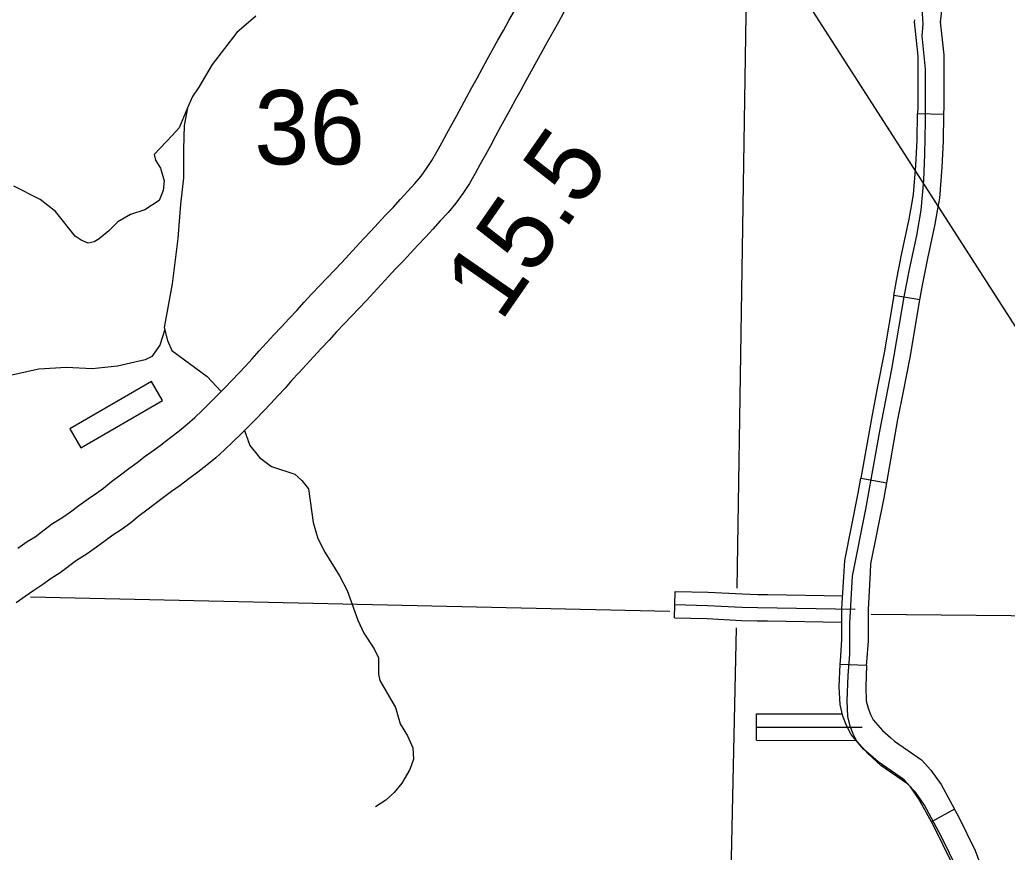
# Model space of a CAD drawing. Extents: x 0 to 3171, y 0 to 2059.
# Drawn here: x 1872.3 to 1965.7, y 1087.6 to 1166.4 of the extents above; entities that cross this region are included whole.
import ezdxf

# ---------------------------------------------------------------- set-up
doc = ezdxf.new("R2010")
doc.units = 0
for name, color, linetype in [('Default', 7, 'Continuous'), ('Level 10', 7, 'Continuous'), ('Level 31', 7, 'Continuous'), ('Level 35', 7, 'Continuous'), ('Level 4', 7, 'Continuous'), ('Level 45', 7, 'Continuous'), ('Level 48', 7, 'Continuous'), ('Level 5', 7, 'Continuous'), ('Level 57', 7, 'Continuous')]:
    doc.layers.add(name, color=color, linetype=linetype)

msp = doc.modelspace()

# ---------------------------------------------------------------- linework, layer by layer
at = {"layer": 'Default'}
for points in [[(1931.872, 1191.314), (2273.758, 658.86), (2637.036, 658.323)], [(1931.872, 1191.314), (2119.81, 898.62)]]:
    msp.add_lwpolyline(points, dxfattribs=at)
at = {"layer": 'Level 10'}
for p, q in [((1885.775, 1126.293), (1885.767, 1126.287)), ((1888.288, 1122.969), (1888.281, 1122.964))]:
    msp.add_line(p, q, dxfattribs=at)
for points in [[(1885.767, 1126.287), (1886.579, 1126.904), (1887.369, 1127.517), (1888.12, 1128.133), (1888.836, 1128.768), (1889.544, 1129.445), (1890.262, 1130.156), (1890.976, 1130.87), (1891.672, 1131.576), (1892.353, 1132.273), (1893.011, 1132.954), (1893.648, 1133.637), (1894.276, 1134.329), (1894.922, 1135.07), (1895.622, 1135.834), (1896.329, 1136.599), (1897.045, 1137.36), (1897.762, 1138.135), (1898.491, 1138.911), (1899.196, 1139.692), (1899.935, 1140.48), (1900.658, 1141.247), (1901.374, 1141.998), (1902.073, 1142.728), (1902.747, 1143.445), (1903.42, 1144.177), (1904.105, 1144.923), (1904.808, 1145.69), (1905.528, 1146.435), (1906.205, 1147.165), (1906.908, 1147.916), (1907.606, 1148.666), (1908.306, 1149.428), (1909.009, 1150.193), (1909.674, 1150.924), (1910.262, 1151.631), (1910.789, 1152.349), (1911.275, 1153.107), (1911.746, 1153.92), (1912.219, 1154.776), (1912.702, 1155.652), (1913.183, 1156.518), (1913.646, 1157.365), (1914.103, 1158.236), (1914.584, 1159.132), (1915.072, 1160.018), (1915.556, 1160.891), (1916.04, 1161.773), (1916.532, 1162.667), (1917.029, 1163.574), (1917.538, 1164.496), (1918.055, 1165.421), (1918.573, 1166.348), (1919.091, 1167.277)], [(1923.782, 1167.164), (1923.26, 1166.208), (1922.734, 1165.255), (1922.211, 1164.317), (1921.693, 1163.39), (1921.181, 1162.473), (1920.679, 1161.565), (1920.184, 1160.662), (1919.692, 1159.767), (1919.205, 1158.879), (1918.719, 1158.002), (1918.244, 1157.141), (1917.784, 1156.285), (1917.32, 1155.398), (1916.832, 1154.505), (1916.347, 1153.635), (1915.868, 1152.764), (1915.373, 1151.867), (1914.833, 1150.937), (1914.226, 1149.989), (1913.545, 1149.063), (1912.818, 1148.188), (1912.083, 1147.381), (1911.375, 1146.61), (1910.665, 1145.837), (1909.954, 1145.073), (1909.254, 1144.325), (1908.554, 1143.57), (1907.842, 1142.834), (1907.175, 1142.106), (1906.488, 1141.358), (1905.8, 1140.609), (1905.095, 1139.859), (1904.387, 1139.12), (1903.683, 1138.381), (1902.971, 1137.625), (1902.262, 1136.869), (1901.555, 1136.088), (1900.811, 1135.294), (1900.091, 1134.517), (1899.376, 1133.757), (1898.689, 1133.013), (1898.029, 1132.293), (1897.39, 1131.559), (1896.714, 1130.815), (1896.032, 1130.085), (1895.343, 1129.371), (1894.646, 1128.657), (1893.931, 1127.933), (1893.201, 1127.203), (1892.45, 1126.459), (1891.66, 1125.704), (1890.825, 1124.962), (1889.968, 1124.26), (1889.116, 1123.599), (1888.288, 1122.969)], [(1872.079, 1116.405), (1872.973, 1117.018), (1873.73, 1117.483), (1875.282, 1118.687), (1876.352, 1119.33), (1877.07, 1119.852), (1877.874, 1120.451), (1878.733, 1121.075), (1879.541, 1121.594), (1880.208, 1122.074), (1880.965, 1122.721), (1881.815, 1123.35), (1882.6, 1123.932), (1883.381, 1124.519), (1884.153, 1125.106), (1884.98, 1125.695), (1885.775, 1126.293)], [(1888.281, 1122.964), (1887.442, 1122.332), (1886.623, 1121.749), (1885.893, 1121.195), (1885.093, 1120.593), (1884.295, 1120.001), (1883.56, 1119.458), (1882.783, 1118.794), (1881.886, 1118.148), (1881.085, 1117.634), (1880.344, 1117.095), (1879.539, 1116.496), (1878.655, 1115.853), (1877.641, 1115.244), (1876.104, 1114.05), (1875.243, 1113.523), (1874.442, 1112.972), (1873.604, 1112.394), (1872.77, 1111.811), (1871.93, 1111.236)]]:
    msp.add_lwpolyline(points, dxfattribs=at)
at = {"layer": 'Level 31'}
for p, q in [((1957.26, 1157.56), (1959.759, 1157.505)), ((1957.484, 1139.917), (1955.019, 1140.333)), ((1951.877, 1123.029), (1954.338, 1122.59)), ((1949.94, 1105.423), (1952.438, 1105.313)), ((1954.727, 1098.431), (1954.727, 1098.431)), ((1960.766, 1091.677), (1958.569, 1090.482))]:
    msp.add_line(p, q, dxfattribs=at)
for points in [[(1959.441, 1166.199), (1959.545, 1167.309), (1959.437, 1169.044), (1958.494, 1172.62), (1958.071, 1174.634), (1958.052, 1175.007)], [(1961.076, 1085.923), (1959.503, 1089.142), (1957.917, 1092.06), (1957.052, 1093.284), (1956.292, 1094.093), (1953.787, 1095.831), (1952.538, 1096.947), (1951.512, 1098.14), (1951.169, 1098.808), (1950.87, 1099.557), (1950.656, 1100.456), (1950.592, 1101.954), (1950.698, 1104.355), (1950.849, 1106.351), (1950.849, 1109.304), (1951.096, 1113.754), (1952.349, 1120.077), (1953.672, 1127.489), (1954.826, 1133.352), (1955.981, 1140.2), (1956.496, 1142.772), (1957.179, 1146.003), (1957.607, 1148.4), (1957.842, 1151.248), (1957.949, 1153.666), (1958.019, 1156.841), (1958.013, 1160.31), (1958.013, 1161.744), (1957.684, 1164.914), (1957.787, 1166.016), (1957.692, 1167.532)], [(1956.952, 1166.431), (1956.932, 1166.22), (1957.267, 1162.991), (1957.267, 1161.621), (1957.273, 1158.166), (1957.26, 1157.56)], [(1959.759, 1157.505), (1959.773, 1158.141), (1959.767, 1161.623), (1959.767, 1163.12), (1959.444, 1166.233), (1959.441, 1166.199)], [(1956.711, 1148.98), (1956.87, 1149.874), (1957.099, 1152.639), (1957.204, 1155.019), (1957.26, 1157.56)], [(1959.172, 1148.541), (1959.352, 1149.55), (1959.594, 1152.481), (1959.703, 1154.936), (1959.759, 1157.505)], [(1955.019, 1140.333), (1955.256, 1141.738), (1955.776, 1144.336), (1956.456, 1147.554), (1956.711, 1148.98)], [(1957.484, 1139.917), (1957.715, 1141.285), (1958.225, 1143.833), (1958.91, 1147.076), (1959.172, 1148.541)], [(1955.019, 1140.333), (1954.101, 1134.889), (1953.474, 1131.705)], [(1955.927, 1131.222), (1956.561, 1134.44), (1957.484, 1139.917)], [(1953.474, 1131.705), (1952.947, 1129.032), (1951.877, 1123.029)], [(1954.338, 1122.59), (1955.405, 1128.571), (1955.927, 1131.222)], [(1950.302, 1114.226), (1950.357, 1115.224), (1951.625, 1121.621), (1951.877, 1123.029)], [(1952.798, 1114.087), (1952.844, 1114.91), (1954.082, 1121.158), (1954.338, 1122.59)], [(1949.94, 1105.423), (1949.954, 1105.741), (1950.103, 1107.711), (1950.103, 1110.651), (1950.302, 1114.226)], [(1952.438, 1105.313), (1952.45, 1105.592), (1952.603, 1107.617), (1952.603, 1110.582), (1952.798, 1114.087)], [(1953.061, 1096.566), (1952.149, 1097.382), (1950.971, 1098.75), (1950.535, 1099.603), (1950.18, 1100.491), (1949.917, 1101.595), (1949.845, 1103.267), (1949.94, 1105.423)], [(1952.438, 1105.313), (1952.348, 1103.266), (1952.404, 1101.941), (1952.569, 1101.248), (1952.813, 1100.639), (1953.061, 1100.154), (1953.936, 1099.137), (1954.727, 1098.431)], [(1954.727, 1098.431), (1955.067, 1098.127), (1957.617, 1096.357), (1958.527, 1095.389), (1959.484, 1094.033), (1960.766, 1091.677)], [(1958.569, 1090.483), (1957.358, 1092.711), (1956.585, 1093.804), (1955.975, 1094.453), (1953.516, 1096.16), (1953.061, 1096.566)], [(1964.306, 1083.436), (1962.732, 1087.727), (1961.118, 1091.027), (1960.766, 1091.677)], [(1961.959, 1082.575), (1960.429, 1086.745), (1958.896, 1089.881), (1958.569, 1090.482)]]:
    msp.add_lwpolyline(points, dxfattribs=at)
at = {"layer": 'Level 35'}
for points in [[(1894.633, 1166.777), (1892.834, 1165.234), (1890.479, 1162.191), (1889.237, 1160.049), (1888.637, 1159.149), (1888.166, 1158.095), (1887.823, 1156.423), (1887.78, 1154.165), (1887.78, 1151.465), (1887.481, 1148.98), (1887.224, 1145.723), (1886.71, 1141.438), (1885.953, 1137.288), (1886.251, 1136.074), (1886.663, 1135.111), (1890.01, 1132.665), (1891.328, 1131.222)], [(1888.166, 1158.095), (1887.352, 1156.209), (1886.71, 1155.481), (1884.997, 1153.681), (1885.125, 1153.124), (1885.597, 1152.366), (1885.939, 1151.165), (1885.853, 1150.265), (1885.468, 1149.322), (1884.097, 1148.423), (1882.769, 1147.994), (1881.57, 1147.308), (1880.689, 1146.436), (1879.799, 1145.691), (1879.319, 1145.402), (1878.738, 1145.278), (1878.084, 1145.554), (1877.513, 1145.948), (1875.651, 1148.261), (1874.22, 1149.412), (1871.705, 1150.667)], [(1885.999, 1137.099), (1885.54, 1135.631), (1884.771, 1134.537), (1884.14, 1134.238), (1883.155, 1134.024), (1881.527, 1133.638), (1879.129, 1133.381), (1876.702, 1133.498), (1874.071, 1133.333), (1867.891, 1131.998), (1864.505, 1130.972), (1863.809, 1130.68)], [(1893.551, 1127.553), (1894.057, 1126.122), (1894.972, 1124.982), (1896.115, 1124.145), (1898.324, 1123.404), (1898.981, 1122.811), (1899.591, 1122.017), (1900.031, 1118.835), (1900.5, 1117.322), (1901.166, 1116.029), (1902.543, 1113.793), (1903.261, 1112.383), (1904.263, 1109.575), (1904.828, 1108.363), (1905.829, 1106.874), (1906.223, 1106.027), (1906.243, 1104.476), (1906.35, 1103.86), (1907.832, 1101.308), (1908.268, 1099.778), (1908.982, 1098.635), (1909.48, 1097.489)], [(1909.48, 1097.489), (1909.543, 1096.422), (1909.189, 1095.45), (1908.455, 1094.156), (1907.7, 1093.263), (1906.926, 1092.552), (1905.934, 1091.906)]]:
    msp.add_lwpolyline(points, dxfattribs=at)
at = {"layer": 'Level 4'}
for points in [[(1941.387, 1191.034), (1940.146, 1112.61)], [(1933.8, 1110.404), (1873.304, 1111.769)], [(1982.641, 1109.82), (1952.859, 1110.129)], [(1940.078, 1108.862), (1938.253, 1024.592), (1938.2, 1022.148), (1937.201, 979.774)]]:
    msp.add_lwpolyline(points, dxfattribs=at)
at = {"layer": 'Level 45'}
for p, q in [((1934.25, 1109.8), (1934.302, 1112.3)), ((1942.017, 1098.212), (1942.02, 1100.712))]:
    msp.add_line(p, q, dxfattribs=at)
for points in [[(1934.302, 1112.3), (1937.423, 1112.235), (1940.689, 1112.064), (1942.137, 1112.023), (1943.091, 1112.007)], [(1943.091, 1112.007), (1950.172, 1111.887)], [(1934.276, 1111.05), (1937.377, 1110.986), (1940.638, 1110.815), (1942.109, 1110.773), (1951.353, 1110.617)], [(1934.25, 1109.8), (1937.331, 1109.737), (1940.588, 1109.566), (1942.081, 1109.524), (1943.049, 1109.507)], [(1943.049, 1109.507), (1950.103, 1109.388)], [(1942.02, 1100.712), (1950.129, 1100.704)], [(1942.018, 1099.462), (1952.016, 1099.452)], [(1942.017, 1098.212), (1951.442, 1098.202)]]:
    msp.add_lwpolyline(points, dxfattribs=at)
at = {"layer": 'Level 57'}
for p, q in [((1884.752, 1132.174), (1876.998, 1127.687)), ((1885.795, 1130.371), (1884.752, 1132.174)), ((1878.041, 1125.884), (1885.795, 1130.371)), ((1876.998, 1127.687), (1878.041, 1125.884))]:
    msp.add_line(p, q, dxfattribs=at)

# ---------------------------------------------------------------- texts
at = {"layer": 'Level 48'}
msp.add_text('15.5', height=7.04, rotation=55.24228, dxfattribs=at).set_placement((1917.804, 1137.731))
at = {"layer": 'Level 5'}
msp.add_text('36', height=7.04, dxfattribs=at).set_placement((1894.466, 1152.734))

doc.saveas('drawing.dxf')
